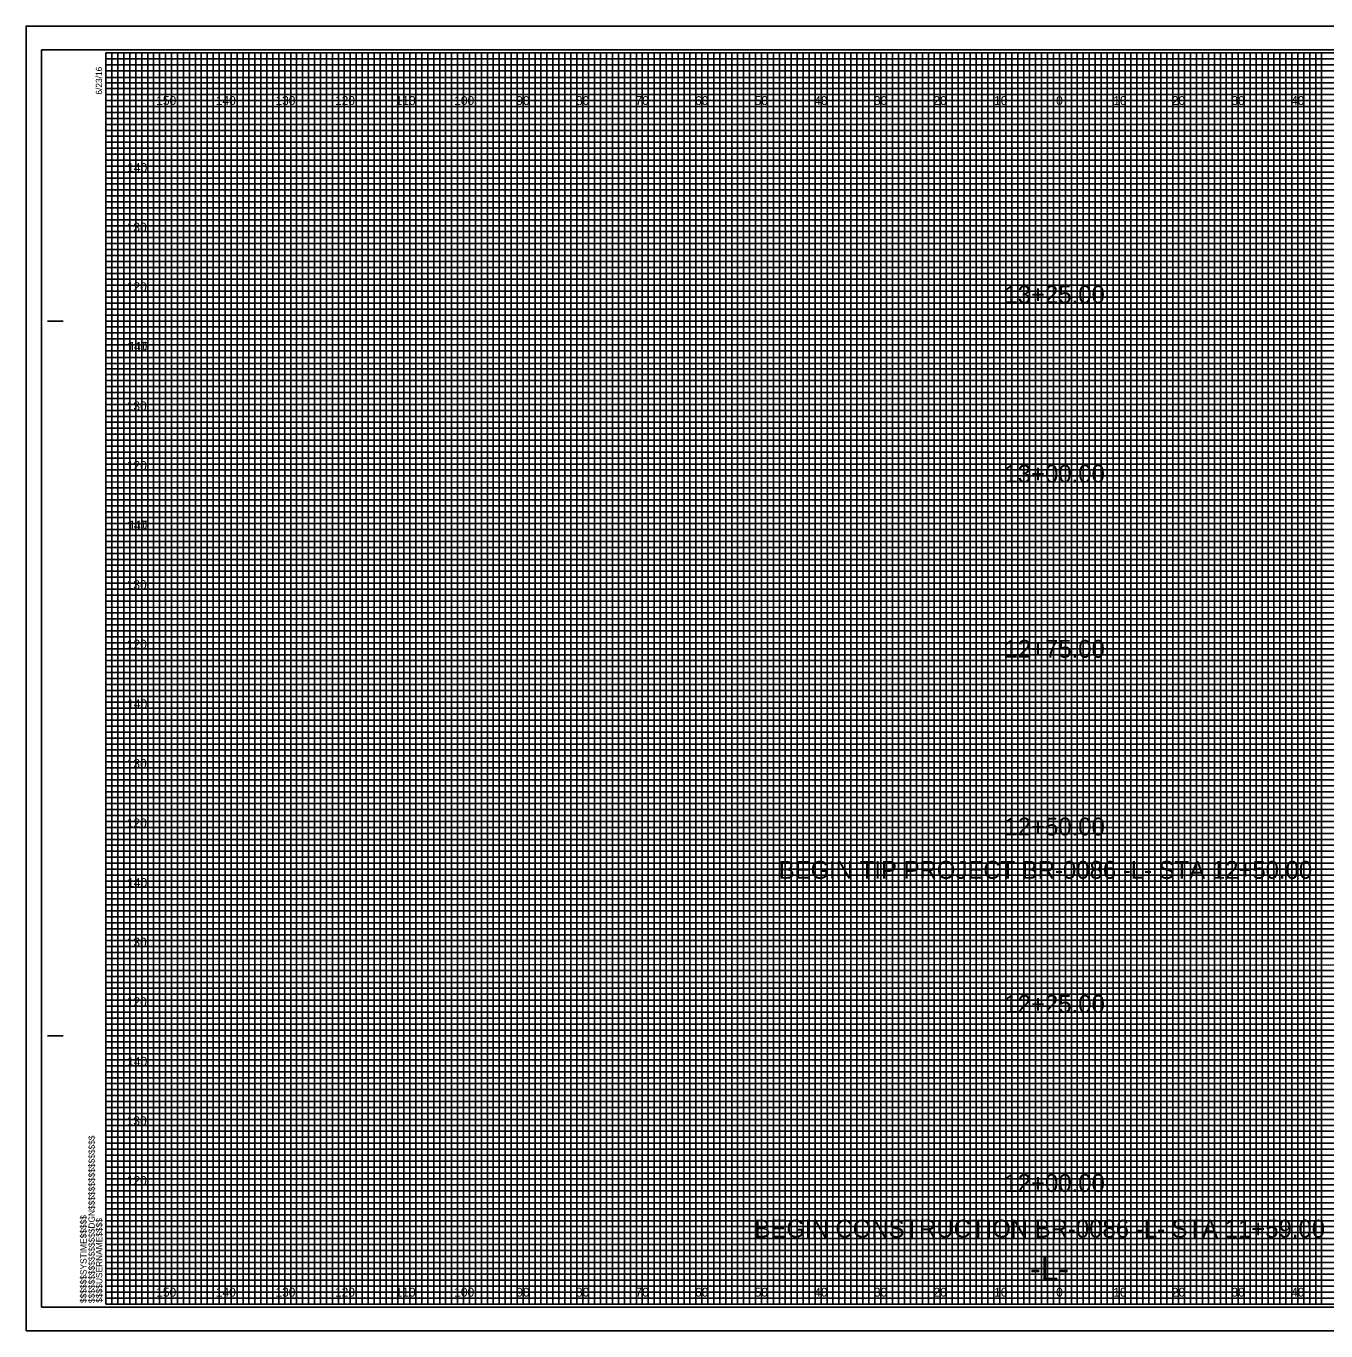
# Model space of a CAD drawing. Extents: x -13 to 371, y -5 to 215.
# Drawn here: x -13.4 to 204.7, y -4.5 to 214.5 of the extents above; entities that cross this region are included whole.
import ezdxf

# ---------------------------------------------------------------- set-up
doc = ezdxf.new("R2010")
doc.units = 0
for name, color, linetype in [('Exist Cross Section Cell', 7, 'Continuous'), ('Exist XS Center Line Elevation Label', 7, 'Continuous'), ('Exist XS Ground Line', 7, 'Continuous'), ('Prop CMT Pvmt Course 1 Wedge', 7, 'Continuous'), ('Prop CMT Pvmt Course 2', 7, 'Continuous'), ('Prop CMT Pvmt Course 2 Wedge', 7, 'Continuous'), ('Prop CMT Pvmt Course 3', 7, 'Continuous'), ('Prop CMT Pvmt Surface', 7, 'Continuous'), ('Prop CMT Shld Paved Course 2', 7, 'Continuous'), ('Prop CMT Shld Paved Course 3', 7, 'Continuous'), ('Prop CMT Slope Grass', 7, 'Continuous'), ('Prop CMT Subgrade Earthwork', 7, 'Continuous'), ('Scratch_Level_0', 7, 'Continuous')]:
    doc.layers.add(name, color=color, linetype=linetype)

msp = doc.modelspace()

# ---------------------------------------------------------------- linework, layer by layer
at = {"layer": 'Exist XS Center Line Elevation Label'}
for points in [[(0, 210), (5, 210), (5, 0), (15, 0), (15, 210), (25, 210), (25, 0), (35, 0), (35, 210), (45, 210), (45, 0), (55, 0), (55, 210), (65, 210), (65, 0), (75, 0), (75, 210), (85, 210), (85, 0), (95, 0), (95, 210), (105, 210), (105, 0), (115, 0), (115, 210), (125, 210), (125, 0), (135, 0), (135, 210), (145, 210), (145, 0), (155, 0), (155, 210), (165, 210), (165, 0), (175, 0), (175, 210), (185, 210), (185, 0), (195, 0), (195, 210), (205, 210)], [(0, 205), (275, 205)], [(0, 185), (320, 185), (320, 195), (0, 195)], [(0, 165), (320, 165), (320, 175), (0, 175)], [(0, 145), (320, 145), (320, 155), (0, 155)], [(0, 125), (320, 125), (320, 135), (0, 135)], [(0, 105), (320, 105), (320, 115), (0, 115)], [(0, 85), (320, 85), (320, 95), (0, 95)], [(0, 65), (320, 65), (320, 75), (0, 75)], [(0, 45), (320, 45), (320, 55), (0, 55)], [(0, 25), (320, 25), (320, 35), (0, 35)], [(0, 5), (320, 5), (320, 15), (0, 15)]]:
    msp.add_lwpolyline(points, dxfattribs=at)
at = {"layer": 'Exist XS Ground Line'}
for p, q in [((10, 210), (0, 210)), ((10, 0), (10, 210)), ((30, 210), (20, 210)), ((20, 210), (20, 0)), ((30, 0), (30, 210)), ((50, 210), (40, 210)), ((40, 210), (40, 0)), ((50, 0), (50, 210)), ((70, 210), (60, 210)), ((60, 210), (60, 0)), ((70, 0), (70, 210)), ((90, 210), (80, 210)), ((80, 210), (80, 0)), ((90, 0), (90, 210)), ((110, 210), (100, 210)), ((100, 210), (100, 0)), ((110, 0), (110, 210)), ((130, 210), (120, 210)), ((120, 210), (120, 0)), ((130, 0), (130, 210)), ((150, 210), (140, 210)), ((140, 210), (140, 0)), ((150, 0), (150, 210)), ((170, 210), (160, 210)), ((160, 210), (160, 0)), ((170, 0), (170, 210)), ((190, 210), (180, 210)), ((180, 210), (180, 0)), ((190, 0), (190, 210)), ((210, 210), (200, 210)), ((200, 210), (200, 0)), ((20, 0), (10, 0)), ((40, 0), (30, 0)), ((60, 0), (50, 0)), ((80, 0), (70, 0)), ((100, 0), (90, 0)), ((120, 0), (110, 0)), ((140, 0), (130, 0)), ((160, 0), (150, 0)), ((180, 0), (170, 0)), ((200, 0), (190, 0))]:
    msp.add_line(p, q, dxfattribs=at)
for points in [[(0, 200), (320, 200), (320, 190), (0, 190)], [(0, 180), (320, 180), (320, 170), (0, 170)], [(0, 160), (320, 160), (320, 150), (0, 150)], [(0, 140), (320, 140), (320, 130), (0, 130)], [(0, 120), (320, 120), (320, 110), (0, 110)], [(0, 100), (320, 100), (320, 90), (0, 90)], [(0, 80), (320, 80), (320, 70), (0, 70)], [(0, 60), (320, 60), (320, 50), (0, 50)], [(0, 40), (320, 40), (320, 30), (0, 30)], [(0, 20), (320, 20), (320, 10), (0, 10)]]:
    msp.add_lwpolyline(points, dxfattribs=at)
at = {"layer": 'Prop CMT Pvmt Course 2'}
for p, q in [((10, 0), (10, 210)), ((20, 0), (20, 210)), ((30, 0), (30, 210)), ((40, 0), (40, 210)), ((50, 0), (50, 210)), ((60, 0), (60, 210)), ((70, 0), (70, 210)), ((80, 0), (80, 210)), ((90, 0), (90, 210)), ((100, 0), (100, 210)), ((110, 0), (110, 210)), ((120, 0), (120, 210)), ((130, 0), (130, 210)), ((140, 0), (140, 210)), ((150, 0), (150, 210)), ((160, 0), (160, 210)), ((170, 0), (170, 210)), ((180, 0), (180, 210)), ((190, 0), (190, 210)), ((200, 0), (200, 210)), ((0, 200), (320, 200)), ((0, 190), (320, 190)), ((0, 180), (320, 180)), ((0, 170), (320, 170)), ((0, 160), (320, 160)), ((0, 150), (320, 150)), ((0, 140), (320, 140)), ((0, 130), (320, 130)), ((0, 120), (320, 120)), ((0, 110), (320, 110)), ((0, 100), (320, 100)), ((0, 90), (320, 90)), ((0, 80), (320, 80)), ((0, 70), (320, 70)), ((0, 60), (320, 60)), ((0, 50), (320, 50)), ((0, 40), (320, 40)), ((0, 30), (320, 30)), ((0, 20), (320, 20)), ((0, 10), (320, 10))]:
    msp.add_line(p, q, dxfattribs=at)
at = {"layer": 'Prop CMT Pvmt Course 3'}
for p, q in [((323.3, 214.5), (-13.4, 214.5)), ((-13.4, 214.5), (-13.4, -4.5)), ((-13.4, -4.5), (323.3, -4.5))]:
    msp.add_line(p, q, dxfattribs=at)
at = {"layer": 'Prop CMT Shld Paved Course 2'}
msp.add_lwpolyline([(-13.4, -4.5), (323.3, -4.5), (323.3, 214.5), (-13.4, 214.5)], close=True, dxfattribs=at)
at = {"layer": 'Prop CMT Shld Paved Course 3'}
msp.add_lwpolyline([(-10.8, -0.5), (322.4, -0.5), (322.4, 210.5), (-10.8, 210.5)], close=True, dxfattribs=at)
at = {"layer": 'Prop CMT Slope Grass'}
for points in [[(0, 0), (1, 0), (1, 210), (2, 210), (2, 0)], [(2, 0), (3, 0), (3, 210), (4, 210), (4, 0)], [(5, 0), (6, 0), (6, 210), (7, 210), (7, 0)], [(7, 0), (8, 0), (8, 210), (9, 210), (9, 0)], [(10, 0), (11, 0), (11, 210), (12, 210), (12, 0)], [(12, 0), (13, 0), (13, 210), (14, 210), (14, 0)], [(15, 0), (16, 0), (16, 210), (17, 210), (17, 0)], [(17, 0), (18, 0), (18, 210), (19, 210), (19, 0)], [(20, 0), (21, 0), (21, 210), (22, 210), (22, 0)], [(22, 0), (23, 0), (23, 210), (24, 210), (24, 0)], [(25, 0), (26, 0), (26, 210), (27, 210), (27, 0)], [(27, 0), (28, 0), (28, 210), (29, 210), (29, 0)], [(30, 0), (31, 0), (31, 210), (32, 210), (32, 0)], [(32, 0), (33, 0), (33, 210), (34, 210), (34, 0)], [(35, 0), (36, 0), (36, 210), (37, 210), (37, 0)], [(37, 0), (38, 0), (38, 210), (39, 210), (39, 0)], [(40, 0), (41, 0), (41, 210), (42, 210), (42, 0)], [(42, 0), (43, 0), (43, 210), (44, 210), (44, 0)], [(45, 0), (46, 0), (46, 210), (47, 210), (47, 0)], [(47, 0), (48, 0), (48, 210), (49, 210), (49, 0)], [(50, 0), (51, 0), (51, 210), (52, 210), (52, 0)], [(52, 0), (53, 0), (53, 210), (54, 210), (54, 0)], [(55, 0), (56, 0), (56, 210), (57, 210), (57, 0)], [(57, 0), (58, 0), (58, 210), (59, 210), (59, 0)], [(60, 0), (61, 0), (61, 210), (62, 210), (62, 0)], [(62, 0), (63, 0), (63, 210), (64, 210), (64, 0)], [(65, 0), (66, 0), (66, 210), (67, 210), (67, 0)], [(67, 0), (68, 0), (68, 210), (69, 210), (69, 0)], [(70, 0), (71, 0), (71, 210), (72, 210), (72, 0)], [(72, 0), (73, 0), (73, 210), (74, 210), (74, 0)], [(75, 0), (76, 0), (76, 210), (77, 210), (77, 0)], [(77, 0), (78, 0), (78, 210), (79, 210), (79, 0)], [(80, 0), (81, 0), (81, 210), (82, 210), (82, 0)], [(82, 0), (83, 0), (83, 210), (84, 210), (84, 0)], [(85, 0), (86, 0), (86, 210), (87, 210), (87, 0)], [(87, 0), (88, 0), (88, 210), (89, 210), (89, 0)], [(90, 0), (91, 0), (91, 210), (92, 210), (92, 0)], [(92, 0), (93, 0), (93, 210), (94, 210), (94, 0)], [(95, 0), (96, 0), (96, 210), (97, 210), (97, 0)], [(97, 0), (98, 0), (98, 210), (99, 210), (99, 0)], [(100, 0), (101, 0), (101, 210), (102, 210), (102, 0)], [(102, 0), (103, 0), (103, 210), (104, 210), (104, 0)], [(105, 0), (106, 0), (106, 210), (107, 210), (107, 0)], [(107, 0), (108, 0), (108, 210), (109, 210), (109, 0)], [(110, 0), (111, 0), (111, 210), (112, 210), (112, 0)], [(112, 0), (113, 0), (113, 210), (114, 210), (114, 0)], [(115, 0), (116, 0), (116, 210), (117, 210), (117, 0)], [(117, 0), (118, 0), (118, 210), (119, 210), (119, 0)], [(120, 0), (121, 0), (121, 210), (122, 210), (122, 0)], [(122, 0), (123, 0), (123, 210), (124, 210), (124, 0)], [(125, 0), (126, 0), (126, 210), (127, 210), (127, 0)], [(127, 0), (128, 0), (128, 210), (129, 210), (129, 0)], [(130, 0), (131, 0), (131, 210), (132, 210), (132, 0)], [(132, 0), (133, 0), (133, 210), (134, 210), (134, 0)], [(135, 0), (136, 0), (136, 210), (137, 210), (137, 0)], [(137, 0), (138, 0), (138, 210), (139, 210), (139, 0)], [(140, 0), (141, 0), (141, 210), (142, 210), (142, 0)], [(142, 0), (143, 0), (143, 210), (144, 210), (144, 0)], [(145, 0), (146, 0), (146, 210), (147, 210), (147, 0)], [(147, 0), (148, 0), (148, 210), (149, 210), (149, 0)], [(150, 0), (151, 0), (151, 210), (152, 210), (152, 0)], [(152, 0), (153, 0), (153, 210), (154, 210), (154, 0)], [(155, 0), (156, 0), (156, 210), (157, 210), (157, 0)], [(157, 0), (158, 0), (158, 210), (159, 210), (159, 0)], [(160, 0), (161, 0), (161, 210), (162, 210), (162, 0)], [(162, 0), (163, 0), (163, 210), (164, 210), (164, 0)], [(165, 0), (166, 0), (166, 210), (167, 210), (167, 0)], [(167, 0), (168, 0), (168, 210), (169, 210), (169, 0)], [(170, 0), (171, 0), (171, 210), (172, 210), (172, 0)], [(172, 0), (173, 0), (173, 210), (174, 210), (174, 0)], [(175, 0), (176, 0), (176, 210), (177, 210), (177, 0)], [(177, 0), (178, 0), (178, 210), (179, 210), (179, 0)], [(180, 0), (181, 0), (181, 210), (182, 210), (182, 0)], [(182, 0), (183, 0), (183, 210), (184, 210), (184, 0)], [(185, 0), (186, 0), (186, 210), (187, 210), (187, 0)], [(187, 0), (188, 0), (188, 210), (189, 210), (189, 0)], [(190, 0), (191, 0), (191, 210), (192, 210), (192, 0)], [(192, 0), (193, 0), (193, 210), (194, 210), (194, 0)], [(195, 0), (196, 0), (196, 210), (197, 210), (197, 0)], [(197, 0), (198, 0), (198, 210), (199, 210), (199, 0)], [(200, 0), (201, 0), (201, 210), (202, 210), (202, 0)], [(202, 0), (203, 0), (203, 210), (204, 210), (204, 0)]]:
    msp.add_lwpolyline(points, dxfattribs=at)
at = {"layer": 'Prop CMT Subgrade Earthwork'}
for p, q in [((-9.8, 165), (-7.3, 165)), ((-9.7, 165), (-7.2, 165)), ((-9.8, 45), (-7.3, 45)), ((-9.7, 45), (-7.2, 45)), ((0, 0), (0, 0)), ((0, 0), (0, 0)), ((0, 0), (0, 0)), ((0, 0), (0, 0)), ((0, 0), (0, 0)), ((0, 0), (0, 0)), ((0, 0), (0, 0))]:
    msp.add_line(p, q, dxfattribs=at)
msp.add_lwpolyline([(320, 210), (0, 210), (0, 0), (320, 0)], close=True, dxfattribs=at)
at = {"layer": 'Scratch_Level_0'}
for p, q in [((0, 209), (260, 209)), ((260, 207.98), (0, 207.98)), ((0, 207.98), (0, 207)), ((0, 207), (260, 207)), ((260, 205.89), (0, 205.89)), ((0, 205.89), (0, 204)), ((0, 204), (320, 204))]:
    msp.add_line(p, q, dxfattribs=at)
for points in [[(0, 203), (270, 203), (320, 203), (320, 202), (0, 202)], [(0, 201), (320, 201), (320, 199), (0, 199)], [(0, 198), (320, 198), (320, 197), (0, 196.98)], [(0, 196), (320, 196), (320, 194), (0, 194)], [(0, 193), (320, 193), (320, 192), (0, 192)], [(0, 191), (320, 191), (320, 189), (0, 189)], [(0, 188), (320, 188), (320, 187), (0, 187)], [(0, 186), (320, 186), (320, 184), (0, 184)], [(0, 183), (320, 183), (320, 182), (0, 182)], [(0, 181), (320, 181), (320, 179), (0, 179)], [(0, 178), (320, 178), (320, 177), (0, 177)], [(0, 176), (320, 176), (320, 173.95), (320, 173), (320, 172), (0, 172)], [(0, 174), (320, 174), (320, 173), (0, 173)], [(0, 171), (320, 171), (320, 169), (0, 169.03)], [(0, 169.03), (320, 169), (320, 168), (0, 168)], [(0, 167), (320, 167), (320, 166), (0, 166)], [(0, 164), (320, 164), (320, 163), (0, 163)], [(0, 162), (320, 162), (320, 161), (0, 161)], [(-0.07, 158.89), (320, 158.89), (320, 157.88), (-0.07, 157.88)], [(0, 157), (320, 157), (320, 156), (0, 156)], [(0, 154), (320, 154), (320, 153), (0, 153)], [(0, 152), (320, 152), (320, 151), (0, 151)], [(0, 149), (320, 149), (320, 148), (0, 148)], [(0, 147), (320, 147), (320, 146), (0, 146)], [(0, 144), (320, 144), (320, 143), (0, 143)], [(0, 142), (320, 142), (320, 141), (0, 141)], [(0, 139), (320, 139), (319.99, 137.98), (0, 138)], [(0, 137), (320, 137), (320, 136), (0, 136)], [(0, 134), (320, 134), (320, 133), (0, 133)], [(0, 132), (320, 132), (320, 131), (0, 131)], [(0, 129), (320, 129), (320, 128), (0, 128)], [(0, 127), (320, 127), (320, 126), (0, 126)], [(0, 124), (320, 124), (320, 123), (0, 123)], [(0, 122), (320, 122), (320, 121), (0, 121)], [(0, 119), (320, 119), (320, 118), (0, 118)], [(0, 116.99), (320.07, 116.91), (320, 116), (0, 116)], [(0, 114), (320, 114), (320, 113), (0, 113)], [(0, 112), (320, 112), (320, 111), (0, 111)], [(0, 109), (320, 109), (320, 108), (0, 108)], [(0, 107), (320, 107), (320, 106), (0, 106)], [(0, 104), (320, 104), (320, 103), (0, 103)], [(0, 102), (320, 102), (320, 101), (0, 101)], [(0, 99), (320, 99), (320, 98), (0, 98)], [(0, 97), (320, 97), (320, 96), (0, 96)], [(0, 94), (320, 94), (320, 93), (0, 93)], [(0, 92), (320, 92), (320, 91), (0, 91)], [(0, 89), (320, 89), (320, 88), (0, 88)], [(0, 87), (320, 87), (320, 86), (0, 86)], [(0, 84), (320, 84), (320, 83), (0, 83)], [(0, 82), (320, 82), (320, 81), (0, 81)], [(0, 79), (320, 79), (319.99, 77.98), (0, 78)], [(0, 77), (320, 77), (320, 76), (0, 76)], [(0, 74), (320, 74), (320, 73), (0, 73)], [(0, 72), (320, 72), (320, 71), (0, 71)], [(0, 69), (320, 69), (320, 68), (0, 68)], [(0, 67), (320, 67), (320, 66), (0, 66)], [(0, 64), (320, 64), (320, 63), (0, 63)], [(0, 62), (320, 62), (320, 61), (0, 61)], [(0, 59), (320, 59), (320, 58), (0, 58)], [(0, 56.99), (320.07, 56.91), (320, 56), (0, 56)], [(0, 54), (320, 54), (320, 53), (0, 53)], [(0, 52), (320, 52), (320, 51), (0, 51)], [(0, 49), (320, 49), (320, 48), (0, 48)], [(0, 47), (320, 47), (320, 46), (0, 46)], [(0, 44), (320, 44), (320, 43), (0, 43)], [(0, 42), (320, 42), (320, 41), (0, 41)], [(0, 39), (320, 39), (320, 38), (0, 38)], [(0, 37), (320, 37), (320, 36), (0, 36)], [(0, 34), (320, 34), (320, 33), (0, 33)], [(0, 32), (320, 32), (320, 31), (0, 31)], [(0, 29), (320, 29), (320, 28), (0, 28)], [(0, 27), (320, 27), (320, 26), (0, 26)], [(0, 24), (320, 24), (320, 23), (0, 23)], [(0, 22), (320, 22), (320, 21), (0, 21)], [(0, 19), (320, 19), (320, 18), (0, 18)], [(0, 17), (320, 17), (320, 16), (0, 16)], [(0, 14), (320, 14), (320, 13), (0, 13)], [(0, 12), (320, 12), (320, 11), (0, 11)], [(0, 9), (320, 9), (320, 8), (0, 8)], [(0, 7), (320, 7), (320, 6), (0, 6)], [(0, 4), (320, 4), (320, 3), (0, 3)], [(0, 2), (320, 2), (320, 1), (0, 1)]]:
    msp.add_lwpolyline(points, dxfattribs=at)

# ---------------------------------------------------------------- texts
at = {"layer": 'Exist Cross Section Cell'}
for s, p in [('150', (8.44, 201.25)), ('140', (18.44, 201.25)), ('130', (28.44, 201.25)), ('120', (38.44, 201.25)), ('110', (48.62, 201.25)), ('100', (58.44, 201.25)), ('90', (68.86, 201.25)), ('80', (78.86, 201.25)), ('70', (88.86, 201.25)), ('60', (98.86, 201.25)), ('50', (108.86, 201.25)), ('40', (118.86, 201.25)), ('30', (128.86, 201.25)), ('20', (138.86, 201.25)), ('10', (149.04, 201.25)), ('0', (159.45, 201.25)), ('0', (159.45, 201.25)), ('10', (169.04, 201.25)), ('20', (178.86, 201.25)), ('30', (188.86, 201.25)), ('40', (198.86, 201.25)), ('150', (8.44, 1.25)), ('140', (18.44, 1.25)), ('130', (28.44, 1.25)), ('120', (38.44, 1.25)), ('110', (48.62, 1.25)), ('100', (58.44, 1.25)), ('90', (68.86, 1.25)), ('80', (78.86, 1.25)), ('70', (88.86, 1.25)), ('60', (98.86, 1.25)), ('50', (108.86, 1.25)), ('40', (118.86, 1.25)), ('30', (128.86, 1.25)), ('20', (138.86, 1.25)), ('10', (149.04, 1.25)), ('0', (159.45, 1.25)), ('0', (159.45, 1.25)), ('10', (169.04, 1.25)), ('20', (178.86, 1.25)), ('30', (188.86, 1.25)), ('40', (198.86, 1.25))]:
    msp.add_text(s, height=1.5, dxfattribs=at).set_placement(p)
at = {"layer": 'Prop CMT Pvmt Course 1 Wedge'}
for s, p in [('140', (3.57, 190)), ('130', (3.49, 180)), ('120', (3.5, 170)), ('140', (3.57, 160)), ('110', (3.88, 160)), ('130', (3.49, 150)), ('120', (3.5, 140)), ('140', (3.57, 130)), ('110', (3.88, 130)), ('130', (3.49, 120)), ('120', (3.5, 110)), ('140', (3.57, 100)), ('130', (3.49, 90)), ('120', (3.5, 80)), ('140', (3.57, 70)), ('130', (3.49, 60)), ('120', (3.5, 50)), ('140', (3.57, 40)), ('130', (3.49, 30)), ('120', (3.5, 20))]:
    msp.add_text(s, height=1.5, dxfattribs=at).set_placement(p)
at = {"layer": 'Prop CMT Pvmt Course 2 Wedge'}
for s, p in [('13+25.00', (150.77, 167.96)), ('13+00.00', (150.77, 137.88)), ('12+75.00', (150.77, 108.48)), ('12+50.00', (150.77, 78.66)), ('BEGIN TIP PROJECT BR-0086 -L- STA 12+50.00', (112.89, 71.38)), ('12+25.00', (150.77, 48.88)), ('12+00.00', (150.77, 18.82)), ('BEGIN CONSTRUCTION BR-0086 -L- STA 11+59.00', (108.82, 11.16))]:
    msp.add_text(s, height=3, dxfattribs=at).set_placement(p)
at = {"layer": 'Prop CMT Pvmt Surface'}
msp.add_text('-L-', height=4, dxfattribs=at).set_placement((155.06, 4))
at = {"layer": 'Prop CMT Subgrade Earthwork'}
for s, p in [('6/23/16', (-0.65, 203)), ('$$$$$$$$$$$$$$$$DGN$$$$$$$$$$$$$$$$', (-1.88, 0.18)), ('$$$$$$SYSTIME$$$$$', (-3.26, 0.18)), ('$$$$USERNAME$$$$', (-0.62, 0.23))]:
    msp.add_text(s, height=1.05, rotation=90, dxfattribs=at).set_placement(p)

doc.saveas('drawing.dxf')
